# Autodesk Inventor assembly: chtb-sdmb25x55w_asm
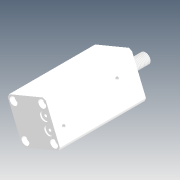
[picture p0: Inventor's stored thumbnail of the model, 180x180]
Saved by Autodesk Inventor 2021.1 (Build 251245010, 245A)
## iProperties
Company: Microsoft
Created: 2018-05
Part Number: chtb-sdmb25x55w_asm
Description: STEP AP214
Document SubType Name: Assembly
Designer: user
Title: chtb-sdmb25x55w_asm.STEP
Author: Windows
Revision Number: ÈÎºÎ
Sending System: SolidWorks 2015
Preprocessor: SwSTEP 2.0
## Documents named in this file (4)
- D:\Vault_2016\Projekty\Clamptek\Hydraulic\CHTB\CHTB-25\Inventor\chtb-sdmb25x55w\chtb-sdmb25x55w_asm.iam
- D:\Vault_2016\Projekty\Clamptek\Hydraulic\CHTB\CHTB-25\Inventor\chtb-sdmb25x55w\CHTB-25QG.ipt
- D:\Vault_2016\Projekty\Clamptek\Hydraulic\CHTB\CHTB-25\Inventor\chtb-sdmb25x55w\CHTB-SDMB25X55NBT.ipt
- D:\Vault_2016\Projekty\Clamptek\Hydraulic\CHTB\CHTB-25\Inventor\chtb-sdmb25x55w\CHTB-SDMB25X55WHSG.ipt
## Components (3 placed, 3 different names)
1. CHTB-25QG_1
2. CHTB-SDMB25X55NBT_2
3. CHTB-SDMB25X55WHSG_3
